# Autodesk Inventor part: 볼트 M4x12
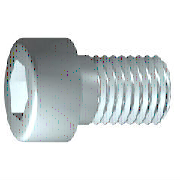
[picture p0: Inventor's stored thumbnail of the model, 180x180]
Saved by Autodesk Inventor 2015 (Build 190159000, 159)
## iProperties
IsCustomPart: 0
Created: 2012-02
Part Number: 볼트 M4x12
Material: 강철, 연강
Description: 6각머리 태핑 나사
Document SubType Name: Modeling
Standard: KS B 1003
Designer: mduedu
Standards Organization: KS
Language: ko-KR
Size Designation: M 4 x 12
Categories: <MemberInstance><Categories><Category DisplayName="조임쇠" InternalName="e4da775c-781d-43d5-af7c-5136215cf5a6" Mnemonic="FSTN"><Category DisplayName="볼트" InternalN
Density: 1 g/cm^3
Appearance: 강철
Author: mduedu
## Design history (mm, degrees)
sketch "스케치1"
  geometry: L1 (-1, 0)-(12, 0); L2 (12, 0)-(12, 2); L3 (12, 2)-(1.75, 2); L4 (1.75, 2)-(1.32, 2); L5 (1.32, 2)-(0, 2); L6 (0, 2)-(0, 3.5); L7 (0, 3.5)-(-4, 3.5); L8 (-4, 3.5)-(-4, 1.732); L9 (-4, 1.732)-(-2, 1.732); L10 (-2, 1.732)-(-1, 0); L11 (-7.2, 0)-(15.2, 0) reference; L12 (0, -0.7)-(0, 4.2) reference; L13 (1.75, 2)-(0, 2)
  constraints: 22 end point, 6 parallel, 2 collinear, 2 perpendicular, 1 horizontal, 1 point on line
  dimensions: "d1" = 10.25 distance from line of L3.end L2 (= GEL); "d2" = 0.42952 distance of L4.end L3.end (computed from GAL); "d3" = 4 distance between parallel lines of L8 L6 (= KOH); "d4" = 2 distance of L8.end L9.end (= INTI); "d5" = 60 deg angle of L10 L1; "d6" = 4 diameter of L3 L1 (= GD); "d7" = 4 diameter of L5 L1 (= BDM); "d8" = 3.4641 diameter of L9 L1 (= 1.1547 x SW); "d9" = 7 diameter of L7 L1 (= KOD); "d26" = 12 distance between parallel lines of L12 L2 (= NLG)
revolve "본체" sketch "스케치1" stored, may be unused: angle "d10" = 90 deg
sketch "스케치2"
  geometry: L1 (0, -4.9)-(0, 4.9) reference; L2 (-4.9, 0)-(4.9, 0) reference; L3 (1.732, 0)-(0.866, -1.5); L4 (0.866, -1.5)-(-0.866, -1.5); L5 (-0.866, -1.5)-(-1.732, 0); L6 (-1.732, 0)-(-0.866, 1.5); L7 (-0.866, 1.5)-(0.866, 1.5); L8 (0.866, 1.5)-(1.732, 0); 2 further points
  constraints: 12 end point, 1 coincident, 1 horizontal alignment, 1 point on line, 12 other
extrude "슬롯" join sketch "스케치2" stored distance "d11" = 10; taper "d12" = 0 deg
workplane "Work Plane1"
fillet "Fillet2" dims "d30" = 0.1 (= R)
body "Solid1"
fillet "모깎기1" dims "d17" = 0.4 (= RR)
feature "스레드" dims "d13" = 10.25 (= GEL), "d14" = 0
chamfer "모따기1" distance "d15" = 0.42941 (= -0.5 x SPD + 0.5 x GD); stored, may be unused: second distance "d16" = 0.42941 (= GUL), angle "d27" = 45 deg
other parameters: "GD" = 4 (= NND) [user parameter; used in 2 equation terms], "NLG" = 12 [user parameter; used in 1 equation term], "GEL" = 10.25 [user parameter; used in 2 equation terms], "KOD" = 7 [user parameter; used in 1 equation term], "KOH" = 4 [user parameter; used in 1 equation term], "INTI" = 2 [user parameter; used in 1 equation term], "GAL" = 0.42941 (= 0.61345 x PTC) [user parameter; used in 1 equation term], "GUL" = 0.42941 (= 0.61345 x PTC) [user parameter; used in 1 equation term], "BDM" = 4 (= NND) [user parameter; used in 1 equation term], "SW" = 3 [user parameter; used in 2 equation terms], "RR" = 0.4 [user parameter; used in 1 equation term], "SPD" = 3.14117 (= NND - 1.2269 x PTC) [user parameter; used in 1 equation term], "d19" = 0, "d28" = 0, "d29" = 0, "R" = 0.1 [user parameter; used in 1 equation term], "PHH" = 0.2 [user parameter], "GD1" = 3.14117 (= THREADDIA - 1.2269 x PTC) [user parameter], "THREADDIA" = 4 [user parameter; used in 1 equation term], "FAWI" = 45 deg [user parameter], "TPU" = 14.28571 (computed from PTC) [user parameter], "PTC" = 0.7 [user parameter; used in 5 equation terms], "NND" = 4 [user parameter; used in 3 equation terms], "TOA" = 30 deg [user parameter], "E0" = 3.465 (= 1.155 x SW) [user parameter]
